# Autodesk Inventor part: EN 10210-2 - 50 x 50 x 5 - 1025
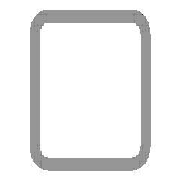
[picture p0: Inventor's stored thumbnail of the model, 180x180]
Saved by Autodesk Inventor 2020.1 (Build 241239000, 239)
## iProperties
_CCFamilyMember: 16
_CCFamilyDisplayName: DIN EN 10210-2 (USAS B17.1 quadratisch) - Rohrleitung — In Klammern angegebene Größen wurden aufgehoben
_FrameMemberDoc: Frame Member File
_Version: 15.0.0
_GetPNFromCC: 1
IsCustomPart: 1
Created: 2019-10
Part Number: EN 10210-2 - 50 x 50 x 5 - 1025
Material: Stahl, weich
Description: Rohrleitung
Document SubType Name: Modeling
Standard: DIN
Designer: lutzd
Standard Revision: 2006-07
Standards Organization: DIN
Language: de-DE
Size Designation: 50 x 50 x 5
Categories: <MemberInstance><Categories><Category DisplayName="Profile" InternalName="089c4875-fa83-4c05-b084-43b9cc11f5ed" Mnemonic="GRDR"><CategoryParameter DisplayName="
Stock Number: 50 x 50 x 5
Mass: 7025.78 g
Surface Area: 3487.5 cm^2
Volume: 895.004 cm^3
Density: 7.85 g/cm^3
Appearance: Halbpoliert
G_W: 50,000 mm
G_H: 50,000 mm
Dimensions: 50x50x1025 mm
Mass: 7,026 kg
DocNumber: ADSK-014203
Folder: .
+9220AE7E-4C79-4A4F-8D4C-34EB6BB42AA6+SCHNITTDETAIL1: Schnittwinkel 90,00 grd
+B23F75BF-99B4-4287-B120-D029925DC7EB+SCHNITTDETAIL3: Schnittwinkel 90,00 grd
G_L: 1025,000 mm
Title: Profil-Bauteil
Author: lutzd
Revision Number: -
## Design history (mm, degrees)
node "Startebene"
node "Endebene"
sketch "Skizze"
  geometry: L1 (-25, -17.5)-(-25, 17.5); L2 (-17.5, 25)-(17.5, 25); L3 (25, 17.5)-(25, -17.5); L4 (17.5, -25)-(-17.5, -25); L5 (-15, 20)-(15, 20); L6 (20, 15)-(20, -15); L7 (15, -20)-(-15, -20); L8 (-20, -15)-(-20, 15); L9 (0, 37.175)-(0, -37.175) reference; L10 (-37.175, 0)-(37.175, 0) reference; A1 r 7.5 centre (-17.5, -17.5) between (-25, -17.5) and (-17.5, -25); A2 r 7.5 centre (-17.5, 17.5) between (-17.5, 25) and (-25, 17.5); A3 r 7.5 centre (17.5, 17.5) between (25, 17.5) and (17.5, 25); A4 r 7.5 centre (17.5, -17.5) between (17.5, -25) and (25, -17.5); A5 r 5 centre (-15, -15) between (-20, -15) and (-15, -20); A6 r 5 centre (-15, 15) between (-15, 20) and (-20, 15); A7 r 5 centre (15, 15) between (20, 15) and (15, 20); A8 r 5 centre (15, -15) between (15, -20) and (20, -15)
  constraints: 16 end point, 16 point on circle, 16 tangent, 8 centre point, 6 equal radius, 4 parallel, 2 perpendicular, 2 other
  dimensions: "d7" = 7.5 radius of A1 (= G_IR); "d10" = 50 distance between parallel lines of L2 L4 (= G_H); "d11" = 50 distance between parallel lines of L1 L3 (= G_W); "d12" = 5 distance between parallel lines of L3 L6 (= G_T); "d15" = 25 distance between parallel lines of L2 L10 (= 0.5 x d10); "d16" = 25 distance between parallel lines of L9 L3 (= 0.5 x d11); "d19" = 5 radius of A5 (= G_T); "d20" = 5 distance between parallel lines of L4 L7 (= G_T)
extrude "Körper" new body sketch "Skizze" stored distance "d3" = 1025 (= G_L); taper "d4" = 0 deg
node "Driven Length"
  sketch "Sketch3"
    geometry: L1 (0, 0)-(10, 0) reference
    constraints: 2 end point, 1 horizontal
  workplane "Work Plane3"
  sketch "Sketch4"
    geometry: L1 (-2, 25)-(12, 25) reference; L2 (-2, 1050)-(12, 1050) reference
    dimensions: "d18" = 1025 distance between parallel lines of L1 L2 (derived)
workplane "Arbeitsebene4"
feature "Trennen1"
workplane "Arbeitsebene6"
feature "Trennen3"
body "Solid1"
other parameters: "G_W" = 50 [user parameter; used in 1 equation term], "G_H" = 50 [user parameter; used in 1 equation term], "G_T" = 5 [user parameter; used in 3 equation terms], "G_IR" = 7.5 [user parameter; used in 1 equation term], "G_L" = 1025 (= d18) [user parameter; used in 1 equation term], "G_OFFSET_START" = -25 [user parameter; used in 1 equation term], "d13" = 25 (= -G_OFFSET_START), "d17" = 90 deg
